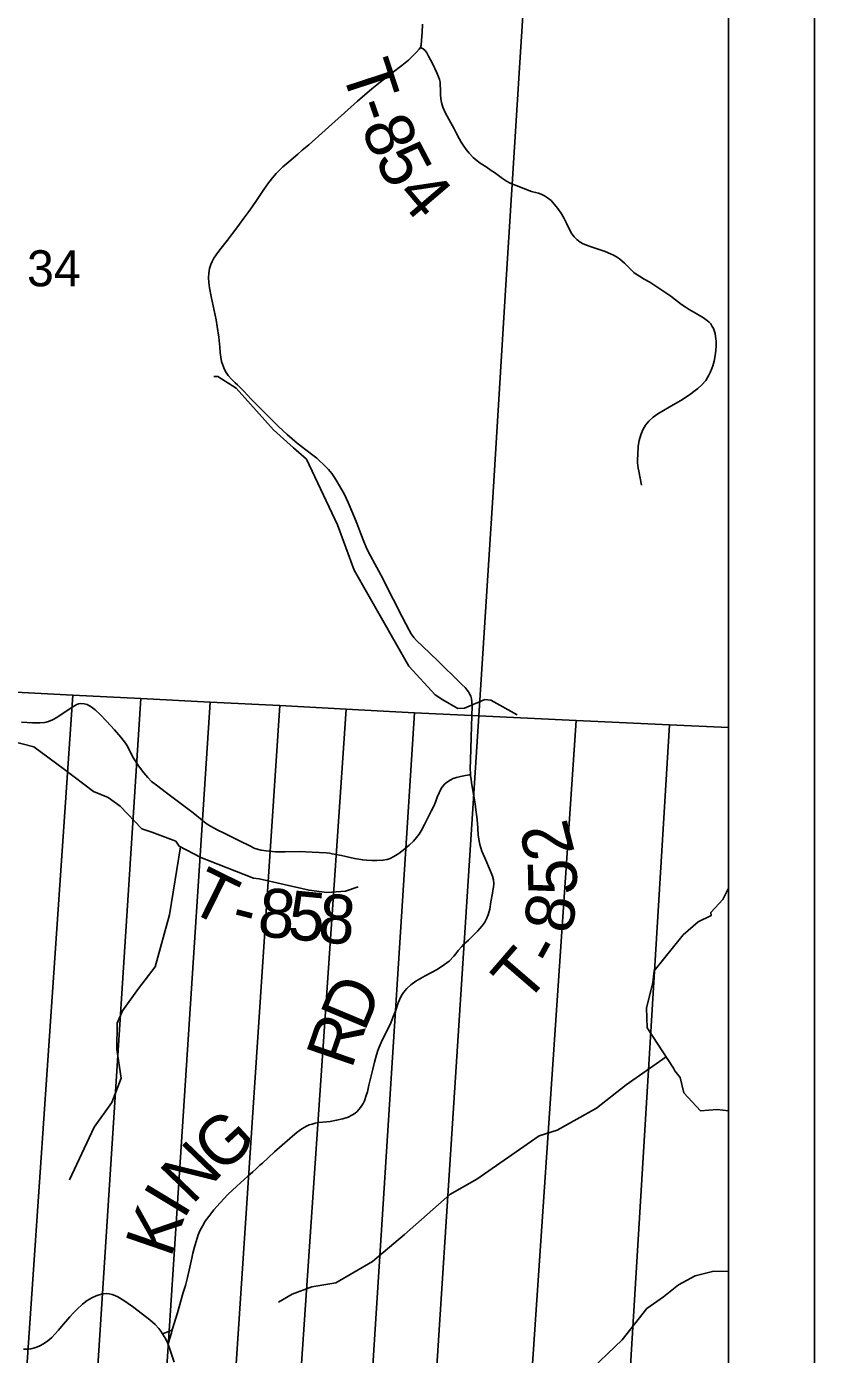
# Model space of a CAD drawing. Extents: x -2.1 to 31.9, y 6.3 to 28.3.
# Drawn here: x 6.019 to 6.934, y 21.982 to 23.525 of the extents above; entities that cross this region are included whole.
import ezdxf

# ---------------------------------------------------------------- set-up
doc = ezdxf.new("R2010")
doc.units = 0
for name, color, linetype in [('Default', 7, 'Continuous'), ('GM_X_County_Road', 7, 'Continuous'), ('GM_X_Minor_River', 7, 'Continuous'), ('GM_X_Section', 7, 'Continuous'), ('GM_X_Section_Text', 7, 'Continuous'), ('GM_X_Township_Road', 7, 'Continuous'), ('GM_X_Township_Road_Text', 7, 'Continuous'), ('SH_Cut_Line', 7, 'Continuous'), ('SH_Data', 7, 'Continuous')]:
    doc.layers.add(name, color=color, linetype=linetype)

msp = doc.modelspace()

# ---------------------------------------------------------------- linework, layer by layer
at = {"layer": 'Default'}
msp.add_lwpolyline([(5.1462, 20.8673), (5.351, 20.8306), (5.3336, 20.8064), (5.2334, 20.7804), (5.2354, 20.7659), (5.3321, 20.7189), (5.4454, 20.7228), (5.4488, 20.7357), (5.4242, 20.7435), (5.4528, 20.7586), (5.5937, 20.7278), (5.7973, 20.6518), (6.0426, 20.5752), (6.4385, 20.4731), (6.4775, 20.444), (6.8344, 20.444), (6.8344, 25.7721)], dxfattribs=at)
msp.add_lwpolyline([(6.8344, 21.8866), (6.8344, 22.7109), (6.7658, 22.714), (6.7023, 21.67), (6.8212, 21.6651)], close=True, dxfattribs=at)
at = {"layer": 'GM_X_County_Road'}
for points in [[(6.1826, 21.9949), (6.1803, 22.0001), (6.1767, 22.0061), (6.1745, 22.0093), (6.1724, 22.0123), (6.168, 22.0173), (6.162, 22.0226), (6.1533, 22.0293), (6.1416, 22.038), (6.1318, 22.0449), (6.1246, 22.0492), (6.1213, 22.0508), (6.1182, 22.0521), (6.1144, 22.0528), (6.111, 22.053), (6.1074, 22.0528), (6.103, 22.0518), (6.0994, 22.0504), (6.0944, 22.0481), (6.0891, 22.0449), (6.0837, 22.0408), (6.0769, 22.0346), (6.0731, 22.0308), (6.0687, 22.0261), (6.059, 22.0149), (6.0555, 22.0105), (6.0514, 22.0059), (6.0479, 22.0021), (6.0434, 21.9981), (6.0384, 21.9946), (6.034, 21.9922), (6.0292, 21.9903), (6.0234, 21.9888), (6.0192, 21.9883), (6.0151, 21.9883)], [(6.1903, 21.9734), (6.1868, 21.9839), (6.1847, 21.9898), (6.1826, 21.9949)]]:
    msp.add_lwpolyline(points, dxfattribs=at)
at = {"layer": 'GM_X_Minor_River'}
for points in [[(6.5888, 22.7254), (6.5584, 22.7426), (6.5513, 22.7432), (6.5275, 22.7333), (6.5199, 22.7328), (6.5025, 22.7429), (6.4936, 22.7488), (6.4629, 22.7821), (6.3993, 22.8938), (6.3801, 22.9465), (6.3439, 23.0228), (6.3288, 23.0358), (6.3056, 23.0567), (6.2621, 23.1052), (6.241, 23.1188), (6.2362, 23.1187)], [(6.4041, 22.5256), (6.3893, 22.5206), (6.3678, 22.5191), (6.347, 22.5217), (6.2888, 22.5348), (6.2823, 22.5356), (6.2211, 22.5598), (6.1961, 22.573), (6.1919, 22.5787), (6.1643, 22.5893), (6.1526, 22.5931), (6.1273, 22.6196), (6.1133, 22.6294), (6.0963, 22.6366), (6.0626, 22.662), (6.027, 22.6885), (5.9983, 22.6957)], [(6.1974, 22.5723), (6.1846, 22.4933), (6.168, 22.4327), (6.1487, 22.4075), (6.1302, 22.3815), (6.1237, 22.3673), (6.1235, 22.3366), (6.1285, 22.3034), (6.1175, 22.2752), (6.0973, 22.2463), (6.0683, 22.1853)], [(6.8018, 22.2653), (6.7827, 22.2863), (6.7785, 22.3041), (6.7721, 22.3117), (6.7706, 22.3151), (6.7399, 22.3618), (6.7391, 22.385), (6.7467, 22.4143), (6.7482, 22.4279), (6.7818, 22.4698), (6.7991, 22.4851), (6.8143, 22.4923), (6.8139, 22.4957), (6.8278, 22.511), (6.8344, 22.524)], [(6.7619, 22.3283), (6.7157, 22.2956), (6.6809, 22.2686), (6.6355, 22.2431), (6.6145, 22.2362), (6.5419, 22.1861), (6.5107, 22.1681), (6.4579, 22.1216), (6.4207, 22.0905), (6.378, 22.0657), (6.3502, 22.0609), (6.3273, 22.0525), (6.3115, 22.0431)], [(6.8344, 22.2656), (6.8213, 22.267), (6.8018, 22.2653)], [(6.8344, 22.0788), (6.8176, 22.0793), (6.7959, 22.0736), (6.7763, 22.0632), (6.7589, 22.0493), (6.7396, 22.0359), (6.7109, 21.9992), (6.6681, 21.9584), (6.6371, 21.9222), (6.6061, 21.8985)]]:
    msp.add_lwpolyline(points, dxfattribs=at)
at = {"layer": 'GM_X_Section'}
for points in [[(6.6083, 23.7379), (6.5918, 23.4837), (6.5759, 23.2313), (6.5607, 22.9782), (6.5442, 22.7242), (6.4695, 22.728), (6.3902, 22.7322), (6.313, 22.7362), (6.2319, 22.7402), (6.1513, 22.7445), (6.0723, 22.7483), (5.9912, 22.7527), (5.9044, 22.7576), (5.8324, 22.7612), (5.7467, 22.7656), (5.664, 22.7698), (5.5827, 22.774), (5.498, 22.7781), (5.5612, 23.7889)], [(6.0723, 22.7483), (6.0006, 21.7019), (5.9213, 21.7055), (5.9912, 22.7527)], [(6.1513, 22.7445), (6.0839, 21.6982), (6.0813, 21.6984), (6.0006, 21.7019), (6.0723, 22.7483)], [(6.2319, 22.7402), (6.1637, 21.6947), (6.0839, 21.6982), (6.1513, 22.7445)], [(6.313, 22.7362), (6.2438, 21.6911), (6.1637, 21.6947), (6.2319, 22.7402)], [(6.3902, 22.7322), (6.3189, 21.6878), (6.2438, 21.6911), (6.313, 22.7362)], [(6.4695, 22.728), (6.4029, 21.6841), (6.3189, 21.6878), (6.3902, 22.7322)], [(6.5442, 22.7242), (6.4767, 21.6808), (6.4029, 21.6841), (6.4695, 22.728)], [(6.6574, 22.719), (6.5865, 21.6746), (6.4767, 21.6808), (6.5442, 22.7242)], [(6.7658, 22.714), (6.7023, 21.67), (6.5865, 21.6746), (6.6574, 22.719)]]:
    msp.add_lwpolyline(points, close=True, dxfattribs=at)
at = {"layer": 'GM_X_Township_Road'}
for points in [[(6.2999, 23.3436), (6.3017, 23.3461), (6.3044, 23.3495), (6.3064, 23.3519), (6.3089, 23.3547), (6.3132, 23.3591), (6.3163, 23.3621), (6.3234, 23.3682), (6.3338, 23.3771), (6.339, 23.3815), (6.3465, 23.388), (6.3656, 23.4048), (6.4032, 23.4384), (6.4198, 23.4531), (6.4295, 23.4606), (6.4435, 23.4714), (6.4549, 23.48), (6.4626, 23.4863), (6.467, 23.4906), (6.4719, 23.4956), (6.4748, 23.4989), (6.4765, 23.501), (6.4772, 23.5036), (6.4778, 23.5093), (6.4785, 23.5185), (6.479, 23.5281)], [(6.7334, 22.9923), (6.7303, 23.0085), (6.7296, 23.012), (6.7291, 23.0152), (6.7289, 23.0182), (6.7288, 23.0226), (6.729, 23.0275), (6.7295, 23.0376), (6.7307, 23.0443), (6.7325, 23.0509), (6.7349, 23.0566), (6.738, 23.062), (6.7419, 23.0668), (6.7469, 23.0715), (6.7525, 23.0754), (6.7654, 23.0829), (6.7809, 23.0921), (6.7907, 23.0986), (6.7942, 23.1012), (6.799, 23.1047), (6.8035, 23.1089), (6.8081, 23.1142), (6.81, 23.1174), (6.8117, 23.1202), (6.8132, 23.1234), (6.815, 23.1278), (6.8162, 23.1311), (6.8178, 23.1365), (6.8191, 23.1432), (6.8199, 23.1487), (6.8201, 23.1543), (6.82, 23.1599), (6.8196, 23.1652), (6.8191, 23.1686), (6.8184, 23.1708), (6.817, 23.1743), (6.8157, 23.1768), (6.8138, 23.1797), (6.8121, 23.1817), (6.8101, 23.1833), (6.8056, 23.1867), (6.797, 23.1917), (6.7889, 23.1966), (6.7842, 23.1996), (6.7799, 23.2024), (6.7728, 23.2078), (6.7673, 23.2119), (6.7627, 23.215), (6.7534, 23.2214), (6.7429, 23.2282), (6.7366, 23.2316), (6.731, 23.2351), (6.7272, 23.2374), (6.7243, 23.2396), (6.7203, 23.2436), (6.7138, 23.2502), (6.7079, 23.2552), (6.7044, 23.2576), (6.7007, 23.2598), (6.6974, 23.2613), (6.6911, 23.264), (6.675, 23.2692), (6.6708, 23.2707), (6.6657, 23.2729), (6.662, 23.2748), (6.6581, 23.2778), (6.6551, 23.2809), (6.6525, 23.2844), (6.6499, 23.2887), (6.6461, 23.2969), (6.6435, 23.3021), (6.6404, 23.3075), (6.6361, 23.314), (6.632, 23.3189), (6.6282, 23.3232), (6.6242, 23.3264), (6.6207, 23.3287), (6.6169, 23.3304), (6.6138, 23.3315), (6.6103, 23.3326), (6.6056, 23.3338), (6.5985, 23.3364), (6.5878, 23.3405), (6.5809, 23.3434), (6.5763, 23.3457), (6.5717, 23.3488), (6.5672, 23.3521), (6.5624, 23.3557), (6.5588, 23.3581), (6.5528, 23.3622), (6.5459, 23.3667), (6.5423, 23.3692), (6.5379, 23.373), (6.533, 23.3781), (6.5294, 23.3824), (6.5259, 23.3875), (6.5236, 23.391), (6.5213, 23.3953), (6.5178, 23.4019), (6.5155, 23.4063), (6.5117, 23.4134), (6.5053, 23.4254), (6.5026, 23.4317), (6.5009, 23.437), (6.5002, 23.4412), (6.4998, 23.4462), (6.4997, 23.4524), (6.4995, 23.4567), (6.4992, 23.4605), (6.4985, 23.4636), (6.4973, 23.467), (6.4956, 23.4714), (6.4904, 23.4825), (6.4858, 23.491), (6.4838, 23.4949), (6.4819, 23.4974), (6.4794, 23.4993), (6.4765, 23.501)], [(6.1826, 21.9949), (6.1836, 21.9964), (6.1843, 21.9981), (6.1849, 21.9999), (6.1869, 22.0075), (6.1879, 22.0111), (6.194, 22.0305), (6.2008, 22.0542), (6.2032, 22.0623), (6.2056, 22.0718), (6.2076, 22.0802), (6.2108, 22.0943), (6.212, 22.1), (6.2141, 22.1087), (6.2156, 22.1137), (6.2181, 22.1212), (6.2204, 22.1267), (6.2233, 22.132), (6.2263, 22.1371), (6.2303, 22.1425), (6.2363, 22.1503), (6.2438, 22.1587), (6.2527, 22.1681), (6.2628, 22.1779), (6.2757, 22.1894), (6.2816, 22.1947), (6.2849, 22.1976), (6.2899, 22.2022), (6.2927, 22.2047), (6.3069, 22.2176), (6.3245, 22.2333), (6.3331, 22.2405), (6.3387, 22.2444), (6.3441, 22.2475), (6.3471, 22.249), (6.3504, 22.2501), (6.3539, 22.2511), (6.3576, 22.2517), (6.363, 22.2523), (6.3713, 22.2529), (6.379, 22.2544), (6.3862, 22.2561), (6.3923, 22.2581), (6.3966, 22.2604), (6.4, 22.2625), (6.4027, 22.2646), (6.4066, 22.2692), (6.4097, 22.2738), (6.4113, 22.2771), (6.4134, 22.2832), (6.4147, 22.2876), (6.4164, 22.2951), (6.4178, 22.3014), (6.4209, 22.3139), (6.423, 22.3221), (6.4252, 22.3306), (6.427, 22.3357), (6.4285, 22.3394), (6.4321, 22.3475), (6.4411, 22.3657), (6.4428, 22.3697), (6.4445, 22.3737), (6.4477, 22.3823), (6.4507, 22.391), (6.4535, 22.3978), (6.455, 22.4006), (6.4567, 22.403), (6.4606, 22.4076), (6.4652, 22.4117), (6.4712, 22.4159), (6.4818, 22.4221), (6.4957, 22.4298), (6.5044, 22.4354), (6.5098, 22.4394), (6.5153, 22.4452), (6.5174, 22.448), (6.5204, 22.4519), (6.5244, 22.4564), (6.5269, 22.4591), (6.5324, 22.4638), (6.5394, 22.4707), (6.5429, 22.4742), (6.5482, 22.4803), (6.5514, 22.4848), (6.5534, 22.4886), (6.5553, 22.4931), (6.557, 22.4997), (6.5584, 22.5082), (6.56, 22.5183), (6.5607, 22.5216), (6.5614, 22.5253), (6.5617, 22.529), (6.5613, 22.5339), (6.5603, 22.5381), (6.5579, 22.5438), (6.5511, 22.5592), (6.5478, 22.5672), (6.5455, 22.5749), (6.5445, 22.5789), (6.5437, 22.5861), (6.543, 22.5933), (6.5427, 22.5996), (6.5419, 22.6069), (6.5409, 22.615), (6.54, 22.622), (6.5393, 22.6268), (6.537, 22.6399), (6.5359, 22.6465), (6.5353, 22.6509), (6.5348, 22.6546), (6.5347, 22.6562), (6.5345, 22.6582), (6.5344, 22.6621), (6.535, 22.6856), (6.5359, 22.7126), (6.5365, 22.7356), (6.5362, 22.7408), (6.5357, 22.744), (6.5349, 22.7471), (6.5336, 22.7501), (6.5322, 22.7523), (6.5308, 22.7543), (6.5284, 22.7572), (6.5245, 22.7609), (6.5194, 22.7657), (6.5124, 22.7727), (6.5068, 22.7783), (6.5017, 22.7834), (6.4966, 22.7882), (6.4872, 22.7972), (6.4717, 22.812), (6.4686, 22.8155), (6.4657, 22.8197), (6.4635, 22.8239), (6.4596, 22.8312), (6.4551, 22.8396), (6.4447, 22.8599), (6.4376, 22.8736), (6.433, 22.883), (6.4279, 22.8926), (6.4234, 22.9011), (6.4185, 22.9104), (6.4143, 22.9185), (6.4107, 22.927), (6.4072, 22.936), (6.4024, 22.9484), (6.398, 22.9594), (6.3925, 22.9721), (6.3877, 22.9822), (6.384, 22.989), (6.3798, 22.9964), (6.3764, 23.0015), (6.3733, 23.0061), (6.3694, 23.0106), (6.3641, 23.016), (6.3583, 23.0214), (6.3558, 23.0238), (6.3514, 23.0273), (6.3432, 23.0334), (6.333, 23.0413), (6.3215, 23.0511), (6.311, 23.0609), (6.2999, 23.072), (6.2886, 23.0836), (6.2797, 23.0925), (6.2711, 23.1015), (6.2672, 23.1054), (6.2637, 23.1089), (6.261, 23.1115), (6.257, 23.1153), (6.253, 23.1199), (6.2505, 23.1235), (6.2487, 23.1267), (6.2466, 23.1318), (6.2453, 23.1362), (6.2443, 23.1412), (6.2436, 23.1465), (6.2432, 23.1528), (6.2421, 23.1645), (6.2402, 23.1766), (6.2388, 23.1847), (6.2332, 23.2115), (6.2313, 23.2218), (6.2304, 23.2277), (6.2301, 23.2332), (6.2304, 23.2387), (6.2313, 23.2441), (6.2328, 23.2488), (6.2344, 23.2524), (6.2364, 23.256), (6.2389, 23.2601), (6.2433, 23.2659), (6.252, 23.2771), (6.2581, 23.2849), (6.2607, 23.2883), (6.2662, 23.2955), (6.2712, 23.3025), (6.278, 23.312), (6.2851, 23.3222), (6.2945, 23.336), (6.2999, 23.3436)], [(6.5347, 22.6562), (6.5333, 22.6559), (6.5288, 22.6549), (6.5231, 22.6538), (6.5184, 22.6526), (6.5144, 22.6515), (6.511, 22.6498), (6.5078, 22.6478), (6.5045, 22.6449), (6.5013, 22.641), (6.4994, 22.6377), (6.4981, 22.635), (6.496, 22.6299), (6.4938, 22.6241), (6.4918, 22.6196), (6.489, 22.6137), (6.4811, 22.5982), (6.4774, 22.5908), (6.475, 22.5868), (6.4719, 22.5829), (6.4685, 22.5789), (6.4634, 22.5742), (6.4584, 22.5698), (6.4514, 22.5645), (6.4456, 22.5608), (6.4413, 22.5588), (6.4377, 22.5576), (6.4329, 22.5566), (6.4256, 22.5561), (6.42, 22.5561), (6.4138, 22.5565), (6.4094, 22.5569), (6.3999, 22.5585), (6.3845, 22.562), (6.3738, 22.5639), (6.3707, 22.5647), (6.3668, 22.5652), (6.3504, 22.5661), (6.3357, 22.5666), (6.3192, 22.5665), (6.3078, 22.5664), (6.2969, 22.5674), (6.2913, 22.5684), (6.2841, 22.5703), (6.2774, 22.5736), (6.2667, 22.5789), (6.2491, 22.5876), (6.2402, 22.592), (6.2365, 22.5938), (6.2325, 22.5962), (6.2275, 22.5994), (6.2206, 22.6046), (6.2124, 22.6118), (6.1967, 22.6234), (6.1797, 22.636), (6.171, 22.6425), (6.1639, 22.6482), (6.1594, 22.6528), (6.1547, 22.6581), (6.1485, 22.6664), (6.1428, 22.6752), (6.1394, 22.6816), (6.1361, 22.6883), (6.1335, 22.6925), (6.1283, 22.6996), (6.1208, 22.7083), (6.1115, 22.7182), (6.1042, 22.726), (6.0982, 22.7312), (6.0937, 22.7349), (6.0891, 22.7375), (6.0857, 22.7383), (6.0818, 22.7387), (6.0789, 22.7382), (6.0761, 22.7373), (6.0722, 22.7347), (6.0612, 22.7273), (6.0537, 22.7223), (6.0487, 22.7199), (6.0442, 22.7179), (6.0397, 22.7167), (6.0338, 22.7161), (6.0255, 22.7162), (6.0127, 22.717)], [(6.1767, 22.0061), (6.1798, 22.0075), (6.1828, 22.0087), (6.1847, 22.0094), (6.1879, 22.0111)]]:
    msp.add_lwpolyline(points, dxfattribs=at)
at = {"layer": 'SH_Cut_Line'}
msp.add_lwpolyline([(5.1462, 20.8673), (5.351, 20.8306), (5.3336, 20.8064), (5.2334, 20.7804), (5.2354, 20.7659), (5.3321, 20.7189), (5.4454, 20.7228), (5.4488, 20.7357), (5.4242, 20.7435), (5.4528, 20.7586), (5.5937, 20.7278), (5.7973, 20.6518), (6.0426, 20.5752), (6.4385, 20.4731), (6.4775, 20.444), (6.8344, 20.444), (6.8344, 27.244)], dxfattribs=at)
at = {"layer": 'SH_Data'}
for p, q in [((6.9344, 27.344), (6.9344, 20.344)), ((6.8344, 27.244), (6.8344, 20.444))]:
    msp.add_line(p, q, dxfattribs=at)

# ---------------------------------------------------------------- texts
at = {"layer": 'GM_X_Section_Text'}
msp.add_text('34', height=0.04186, rotation=0, dxfattribs=at).set_placement((6.0191, 23.2235))
at = {"layer": 'GM_X_Township_Road_Text'}
for s, rotation, p in [('T', 288.1334, (6.3841, 23.4753)), ('-', 289.1162, (6.3976, 23.4339)), ('8', 292.8593, (6.4067, 23.4081)), ('5', 297.6236, (6.4225, 23.3712)), ('4', 310.4716, (6.4465, 23.3287)), ('2', 104.1915, (6.6561, 22.5656)), ('T', 333.732, (6.2037, 22.4994)), ('5', 91.23, (6.6587, 22.5167)), ('8', 354.3683, (6.2858, 22.4687)), ('5', 354.5678, (6.3208, 22.4653)), ('8', 354.7543, (6.3559, 22.4619)), ('8', 79.4972, (6.6513, 22.4697)), ('-', 345.7027, (6.254, 22.4761)), ('T', 49.1872, (6.5982, 22.3879)), ('-', 61.175, (6.6334, 22.4307)), ('D', 67.2914, (6.4112, 22.356)), ('R', 70.9763, (6.3963, 22.3128)), ('G', 42.6863, (6.2451, 22.1907)), ('N', 46.0162, (6.211, 22.1553)), ('I', 58.8481, (6.201, 22.138)), ('K', 70.9988, (6.186, 22.0936))]:
    msp.add_text(s, height=0.0568, rotation=rotation, dxfattribs=at).set_placement(p)

doc.saveas('drawing.dxf')
